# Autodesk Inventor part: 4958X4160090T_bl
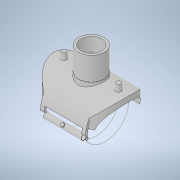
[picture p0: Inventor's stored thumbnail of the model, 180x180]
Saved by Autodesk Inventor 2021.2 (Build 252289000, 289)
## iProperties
Created: 2020-06
Part Number: 4958X4160090T_bl
Material: Generic
Description: Plasson Branch Saddle 160x90
Document SubType Name: Modeling
Designer: KIM
Density: 1 g/cm^3
Appearance: Default
Author: KIM
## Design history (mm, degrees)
derived "4958X4.ipt"
feature "Solid1::4958X4.ipt" dims "ScaleForDerivedMember" = 10
tag "TaggingFeature1"
body "Solid1"
other parameters: "d0" = 263 [user parameter], "d3" = 197.2 [user parameter], "d4" = 107 [user parameter], "d7" = 73 [user parameter], "d9" = 81 [user parameter], "d10" = 0.5 [user parameter], "d11" = 1 [user parameter], "d12" = 26.75 [user parameter], "d13" = 16 [user parameter], "d14" = 8 [user parameter], "d16" = 10 deg [user parameter], "d17" = 10 deg [user parameter], "d19" = 0 [user parameter], "d23" = 0 [user parameter], "d26" = 0 [user parameter], "d27" = 157.8 [user parameter], "d28" = 0 [user parameter], "d29" = 131.5 [user parameter], "d30" = 0 [user parameter], "d31" = 1 [user parameter], "d32" = 1 [user parameter], "d33" = 19.2 [user parameter], "d34" = 9.6 [user parameter], "d35" = 45 deg [user parameter], "d36" = 131.5 [user parameter], "d37" = 0 [user parameter], "d38" = 5 [user parameter], "d39" = 85 deg [user parameter], "d40" = 26.75 [user parameter], "d41" = 16 [user parameter], "d42" = 95.63636 [user parameter], "d49" = 3 [user parameter], "d50" = 6 [user parameter], "d51" = 5 [user parameter], "d54" = 0 [user parameter], "d57" = 35 deg [user parameter], "d60" = 16.4375 [user parameter], "d61" = 1 [user parameter], "d62" = 90 deg [user parameter], "d63" = 2 [user parameter], "d64" = 0 [user parameter], "d65" = 0 [user parameter], "d68" = 32.875 [user parameter], "d70" = 0.57711 [user parameter], "d71" = 10 deg [user parameter], "d73" = 6.51 [user parameter], "B" = 222 [user parameter], "L" = 263 [user parameter], "LS" = 81 [user parameter], "H1" = 107 [user parameter], "Dt" = 16 [user parameter], "di" = 73 [user parameter], "d72" = 18.6 [user parameter]
